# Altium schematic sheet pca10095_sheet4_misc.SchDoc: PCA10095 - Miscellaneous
size A3; Organization: Nordic Semiconductor; DocumentNumber: 4; SheetNumber: 4; SheetTotal: 6; CompanyName: Nordic Semiconductor
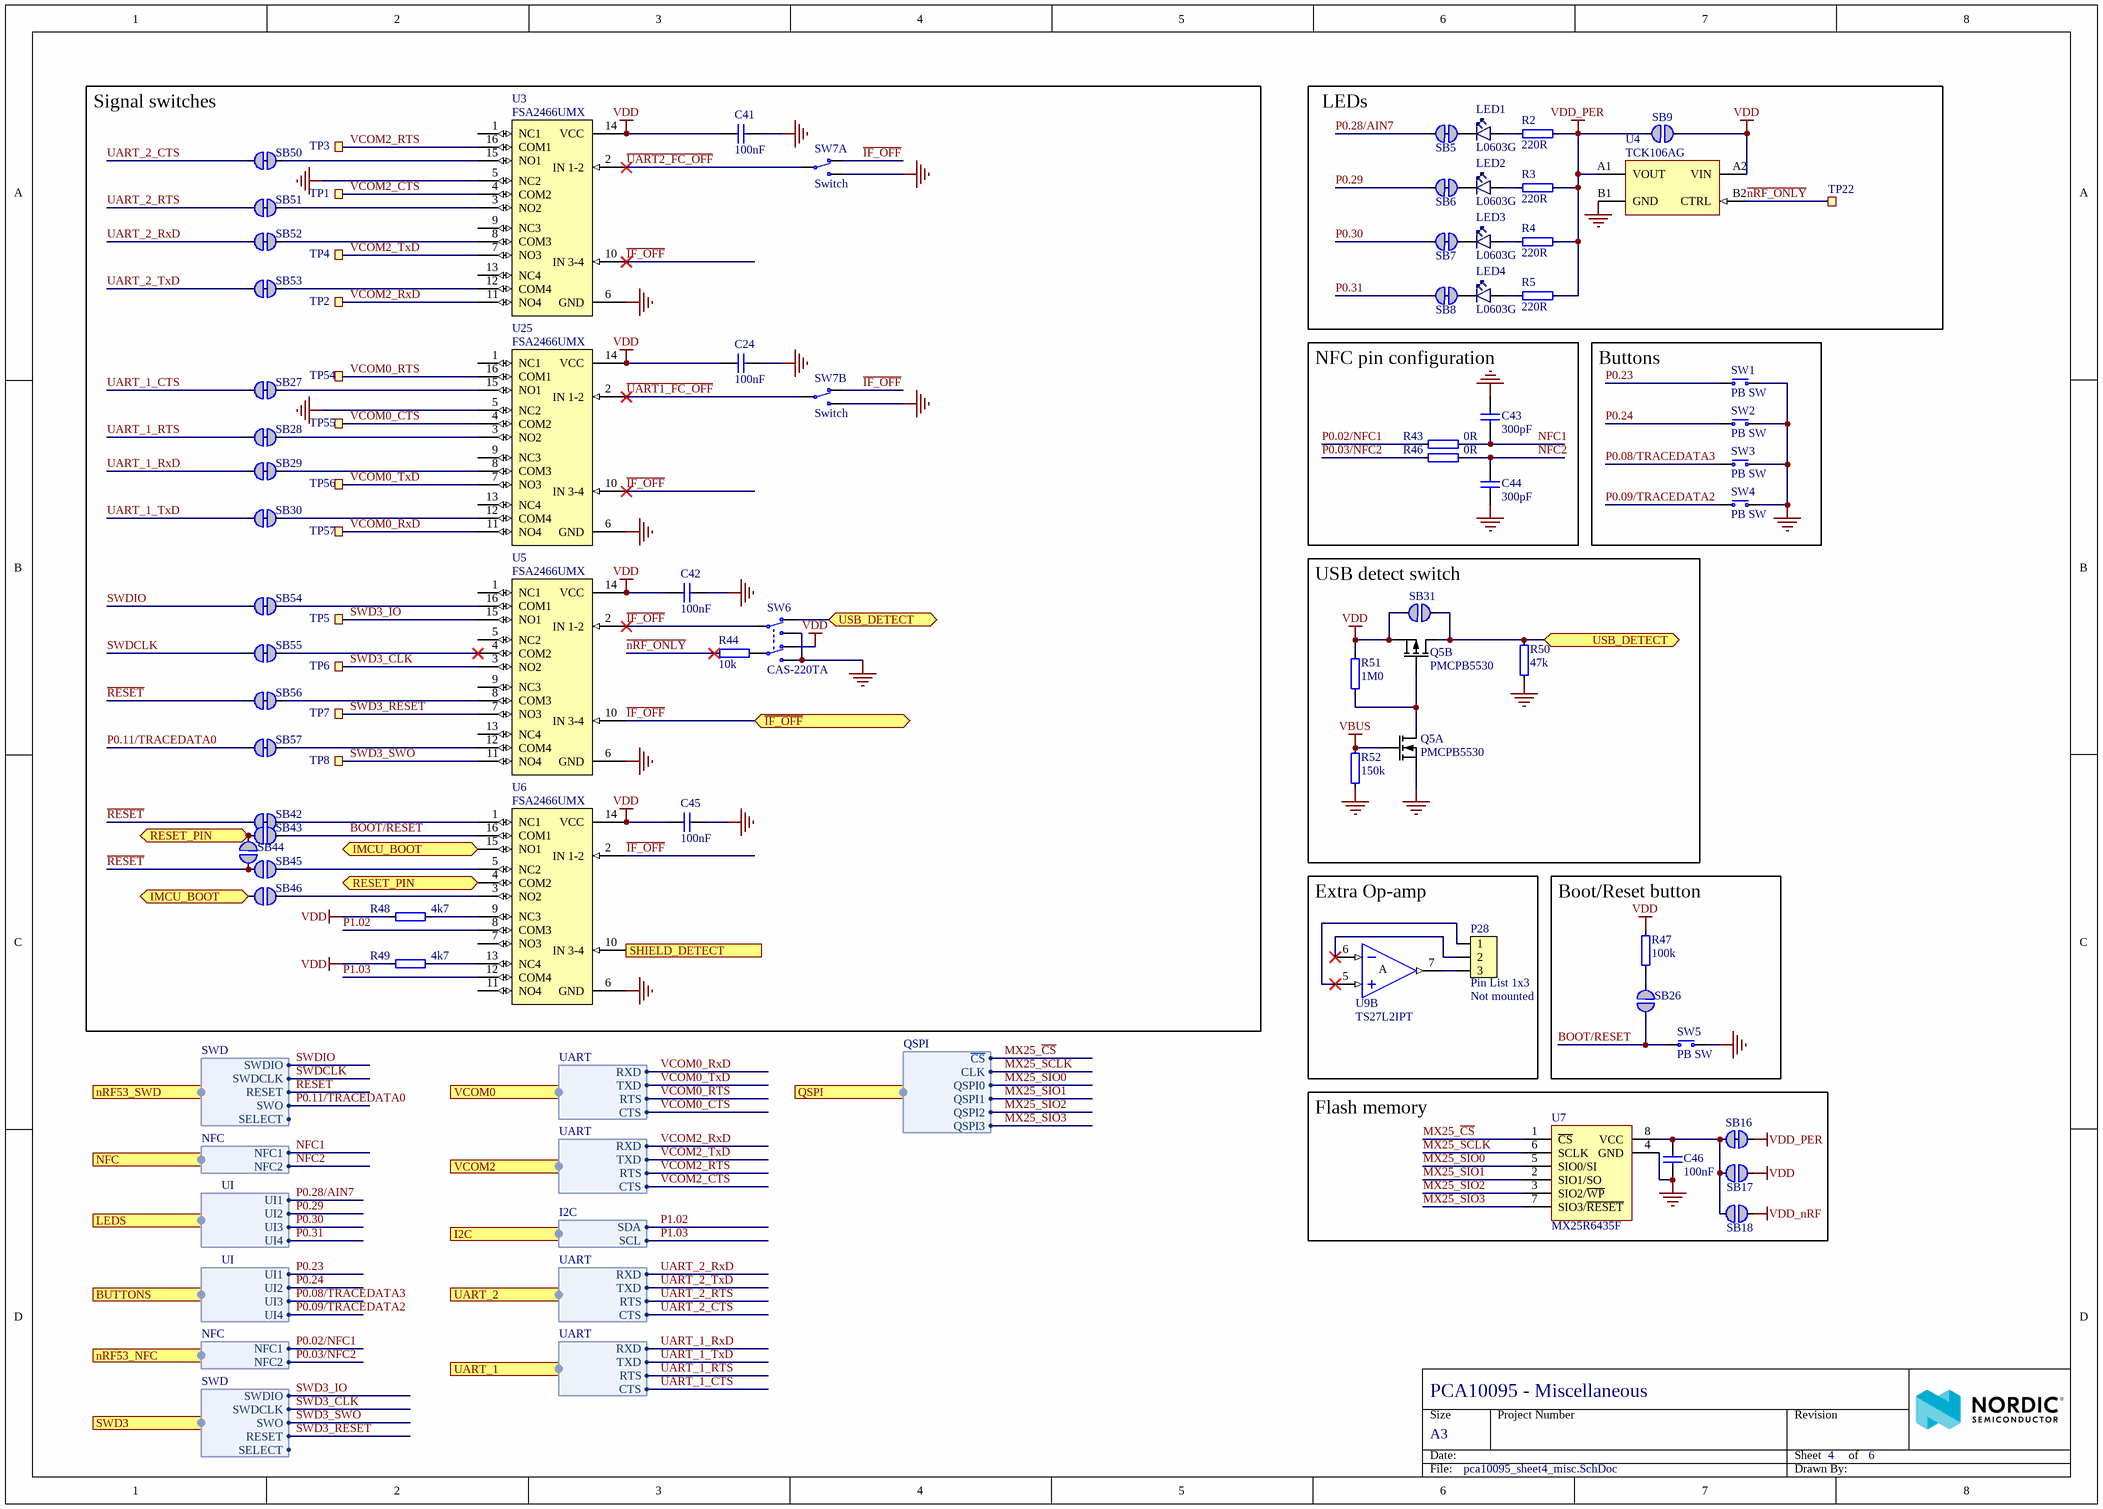
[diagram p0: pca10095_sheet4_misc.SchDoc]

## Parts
C24  100nF  [CAPC0603X03L_C]
C41  100nF  [CAPC0603X03L_C]
C42  100nF  [CAPC0603X03L_C]
C43  300pF  [CAPC1005X04L]
C44  300pF  [CAPC1005X04L]
C45  100nF  [CAPC0603X03L_C]
C46  100nF  [CAPC0603X03L_C]
LED1  L0603G  [LED_0603_G]
LED2  L0603G  [LED_0603_G]
LED3  L0603G  [LED_0603_G]
LED4  L0603G  [LED_0603_G]
P28  Pin List 1x3  Assembly: Not mounted  [LIST_1x3-NC]
Q5  PMCPB5530  [PMCPB5530X]  (parts A,B of 2)
R2  220R  [RESC0603X03L_C]
R3  220R  [RESC0603X03L_C]
R4  220R  [RESC0603X03L_C]
R5  220R  [RESC0603X03L_C]
R43  0R  [RESC0603X03L_C]
R44  10k  [RESC0603X03L_C]
R46  0R  [RESC0603X03L_C]
R47  100k  [RESC0603X03L_C]
R48  4k7  [RESC0603X03L_C]
R49  4k7  [RESC0603X03L_C]
R50  47k  [RESC0603X03L_C]
R51  1M0  [RESC0603X03L_C]
R52  150k  [RESC0603X03L_C]
SB5  Solderbridge  [Solderbridge_Shorted]  (value not drawn)  (net tie, no BOM)
SB6  Solderbridge  [Solderbridge_Shorted]  (value not drawn)  (net tie, no BOM)
SB7  Solderbridge  [Solderbridge_Shorted]  (value not drawn)  (net tie, no BOM)
SB8  Solderbridge  [Solderbridge_Shorted]  (value not drawn)  (net tie, no BOM)
SB9  Solderbridge  [Solderbridge]  (value not drawn)  (no BOM)
SB16  Solderbridge  [Solderbridge_Shorted]  (value not drawn)  (net tie, no BOM)
SB17  Solderbridge  [Solderbridge]  (value not drawn)  (no BOM)
SB18  Solderbridge  [Solderbridge]  (value not drawn)  (no BOM)
SB26  Solderbridge  [Solderbridge]  (value not drawn)  (no BOM)
SB27  Solderbridge  [Solderbridge_Shorted]  (value not drawn)  (net tie, no BOM)
SB28  Solderbridge  [Solderbridge_Shorted]  (value not drawn)  (net tie, no BOM)
SB29  Solderbridge  [Solderbridge_Shorted]  (value not drawn)  (net tie, no BOM)
SB30  Solderbridge  [Solderbridge_Shorted]  (value not drawn)  (net tie, no BOM)
SB31  Solderbridge  [Solderbridge]  (value not drawn)  (no BOM)
SB42  Solderbridge  [Solderbridge_Shorted]  (value not drawn)  (net tie, no BOM)
SB43  Solderbridge  [Solderbridge]  (value not drawn)  (no BOM)
SB44  Solderbridge  [Solderbridge]  (value not drawn)  (no BOM)
SB45  Solderbridge  [Solderbridge]  (value not drawn)  (no BOM)
SB46  Solderbridge  [Solderbridge]  (value not drawn)  (no BOM)
SB50  Solderbridge  [Solderbridge_Shorted]  (value not drawn)  (net tie, no BOM)
SB51  Solderbridge  [Solderbridge_Shorted]  (value not drawn)  (net tie, no BOM)
SB52  Solderbridge  [Solderbridge_Shorted]  (value not drawn)  (net tie, no BOM)
SB53  Solderbridge  [Solderbridge_Shorted]  (value not drawn)  (net tie, no BOM)
SB54  Solderbridge  [Solderbridge_Shorted]  (value not drawn)  (net tie, no BOM)
SB55  Solderbridge  [Solderbridge_Shorted]  (value not drawn)  (net tie, no BOM)
SB56  Solderbridge  [Solderbridge_Shorted]  (value not drawn)  (net tie, no BOM)
SB57  Solderbridge  [Solderbridge_Shorted]  (value not drawn)  (net tie, no BOM)
SW1  PB SW  [Switch-PB-6.2x6.3mm-SMD]
SW2  PB SW  [Switch-PB-6.2x6.3mm-SMD]
SW3  PB SW  [Switch-PB-6.2x6.3mm-SMD]
SW4  PB SW  [Switch-PB-6.2x6.3mm-SMD]
SW5  PB SW  [Switch-PB-6.2x6.3mm-SMD]
SW6  CAS-220TA  [CAS-220TA]
SW7  Switch  [CAS-D20A]  (parts A,B of 2)
TP1  Ø1.5mm,SMD  [TP_SMD_Ø1.5mm]  (value not drawn)  (no BOM)
TP2  Ø1.5mm,SMD  [TP_SMD_Ø1.5mm]  (value not drawn)  (no BOM)
TP3  Ø1.5mm,SMD  [TP_SMD_Ø1.5mm]  (value not drawn)  (no BOM)
TP4  Ø1.5mm,SMD  [TP_SMD_Ø1.5mm]  (value not drawn)  (no BOM)
TP5  Ø1.5mm,SMD  [TP_SMD_Ø1.5mm]  (value not drawn)  (no BOM)
TP6  Ø1.5mm,SMD  [TP_SMD_Ø1.5mm]  (value not drawn)  (no BOM)
TP7  Ø1.5mm,SMD  [TP_SMD_Ø1.5mm]  (value not drawn)  (no BOM)
TP8  Ø1.5mm,SMD  [TP_SMD_Ø1.5mm]  (value not drawn)  (no BOM)
TP22  Ø1.5mm,SMD  [TP_SMD_Ø1.5mm]  (value not drawn)  (no BOM)
TP54  Ø1.5mm,SMD  [TP_SMD_Ø1.5mm]  (value not drawn)  (no BOM)
TP55  Ø1.5mm,SMD  [TP_SMD_Ø1.5mm]  (value not drawn)  (no BOM)
TP56  Ø1.5mm,SMD  [TP_SMD_Ø1.5mm]  (value not drawn)  (no BOM)
TP57  Ø1.5mm,SMD  [TP_SMD_Ø1.5mm]  (value not drawn)  (no BOM)
U3  FSA2466UMX  [XQFN40P180X260X50-16N]
U4  TCK106AG  [BGA4C40P2X2_76X76X62]
U5  FSA2466UMX  [XQFN40P180X260X50-16N]
U6  FSA2466UMX  [XQFN40P180X260X50-16N]
U7  MX25R6435F  [SON127P600X80_HS-9N]
U9  TS27L2IPT  [TSOP65P640X120-8N]  (part B of 2)
U25  FSA2466UMX  [XQFN40P180X260X50-16N]

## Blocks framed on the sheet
Signal switches: C24 C41 C42 C45 R44 R48 R49 SB27-SB30 SB42-SB46 SB50-SB57 SW6 SW7 TP1-TP8 TP54-TP57 U3 U5 U6 U25
LEDs: LED1-LED4 R2-R5 SB5-SB9 TP22 U4
NFC pin configuration: C43 C44 R43 R46
Buttons: SW1-SW4
USB detect switch: Q5 R50-R52 SB31
Extra Op-amp: P28 U9
Boot/Reset button: R47 SB26 SW5
Flash memory: C46 SB16-SB18 U7

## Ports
BUTTONS (harness UI), I2C (harness I2C), IMCU_BOOT (bidir), LEDS (harness UI), NFC (harness NFC), nRF53_NFC (harness NFC), nRF53_SWD (harness SWD), QSPI (harness QSPI), RESET_PIN (bidir), SHIELD_DETECT (in), SWD3 (harness SWD), UART_1 (harness UART), UART_2 (harness UART), USB_DETECT (bidir), VCOM0 (harness UART), VCOM2 (harness UART), ~{IF_OFF} (bidir)

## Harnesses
SWD: SWDIO, SWDCLK, SWO, RESET, SELECT
NFC: NFC2, NFC1
UI: UI4, UI3, UI2, UI1
QSPI: ~{CS}, QSPI0, CLK, QSPI1, QSPI2, QSPI3
UART: RTS, CTS, RXD, TXD
I2C: SCL, SDA

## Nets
GND: C24.1 C41.1 C42.1 C43.2 C44.1 C45.1 C46.1 Q5.1(S1) R50.2 R52.2 SW1.1(N.O) SW2.1(N.O) SW3.1(N.O) SW4.1(N.O) SW5.1(N.O) SW6.1(N.O-1) SW6.4(N.O-2) SW7.1(N.O) SW7.4(N.O) U3.5(NC2) U3.6(GND) U4.B1(GND) U5.6(GND) U6.6(GND) U7.4(GND) U7.9(GND) U25.5(NC2) U25.6(GND)
VBUS: Q5.2(G1) R52.1
VDD: C24.2 C41.2 C42.2 C45.2 Q5.4(S2) R47.2 R48.1 R49.1 R51.1 SB9.1 SB17.1 SB31.1 SW6.6(N.C-2) U3.14(VCC) U4.A2(VIN) U5.14(VCC) U6.14(VCC) U25.14(VCC)
VDD_nRF: SB18.1
VDD_PER: R2.2 R3.2 R4.2 R5.2 SB9.2 SB16.1 U4.A1(VOUT)
BOOT/RESET: SB26.1 SB43.1 SW5.2(COM) U6.16(COM1)
~{IF_OFF}: SW6.2(COM-1) SW7.3(N.C) SW7.6(N.C) U3.10(IN_3-4) U5.2(IN_1-2) U5.10(IN_3-4) U6.2(IN_1-2) U25.10(IN_3-4) ; port ~{IF_OFF}
IMCU_BOOT: SB46.2 U6.15(NO1) ; port IMCU_BOOT
MX25_~{CS}: U7.1(~{CS}) ; port QSPI.~{CS}
MX25_SCLK: U7.6(SCLK) ; port QSPI.CLK
MX25_SIO0: U7.5(SIO0/SI) ; port QSPI.QSPI0
MX25_SIO1: U7.2(SIO1/SO) ; port QSPI.QSPI1
MX25_SIO2: U7.3(SIO2/~{WP}) ; port QSPI.QSPI2
MX25_SIO3: U7.7(SIO3/~{RESET}) ; port QSPI.QSPI3
~{nRF_ONLY}: R44.1 TP22.1 U4.B2(CTRL)
NFC1: C43.1 R43.1 ; port NFC.NFC1
NFC2: C44.2 R46.1 ; port NFC.NFC2
P0.02/NFC1: R43.2 ; port nRF53_NFC.NFC1
P0.03/NFC2: R46.2 ; port nRF53_NFC.NFC2
P0.08/TRACEDATA3: SW3.2(COM) ; port BUTTONS.UI3
P0.09/TRACEDATA2: SW4.2(COM) ; port BUTTONS.UI4
P0.11/TRACEDATA0: SB57.1 ; port nRF53_SWD.SWO
P0.23: SW1.2(COM) ; port BUTTONS.UI1
P0.24: SW2.2(COM) ; port BUTTONS.UI2
P0.28/AIN7: SB5.1 ; port LEDS.UI1
P0.29: SB6.1 ; port LEDS.UI2
P0.30: SB7.1 ; port LEDS.UI3
P0.31: SB8.1 ; port LEDS.UI4
P1.02: U6.8(COM3) ; port I2C.SDA
P1.03: U6.12(COM4) ; port I2C.SCL
~{RESET}: SB42.2 SB44.2 SB45.2 SB56.1 ; port nRF53_SWD.RESET
RESET_PIN: SB43.2 SB44.1 U6.4(COM2) ; port RESET_PIN
SHIELD_DETECT: U6.10(IN_3-4) ; port SHIELD_DETECT
SWD3_CLK: TP6.1 U5.3(NO2) ; port SWD3.SWDCLK
SWD3_IO: TP5.1 U5.15(NO1) ; port SWD3.SWDIO
SWD3_RESET: TP7.1 U5.7(NO3) ; port SWD3.RESET
SWD3_SWO: TP8.1 U5.11(NO4) ; port SWD3.SWO
SWDCLK: SB55.1 ; port nRF53_SWD.SWDCLK
SWDIO: SB54.1 ; port nRF53_SWD.SWDIO
~{UART1_FC_OFF}: SW7.5(COM) U25.2(IN_1-2)
~{UART2_FC_OFF}: SW7.2(COM) U3.2(IN_1-2)
UART_1_CTS: SB27.1 ; port UART_1.CTS
UART_1_RTS: SB28.1 ; port UART_1.RTS
UART_1_RxD: SB29.1 ; port UART_1.RXD
UART_1_TxD: SB30.1 ; port UART_1.TXD
UART_2_CTS: SB50.1 ; port UART_2.CTS
UART_2_RTS: SB51.1 ; port UART_2.RTS
UART_2_RxD: SB52.1 ; port UART_2.RXD
UART_2_TxD: SB53.1 ; port UART_2.TXD
USB_DETECT: Q5.3(D2) R50.1 SB31.2 SW6.3(N.C-1) ; port USB_DETECT
VCOM0_CTS: TP55.1 U25.4(COM2) ; port VCOM0.CTS
VCOM0_RTS: TP54.1 U25.16(COM1) ; port VCOM0.RTS
VCOM0_RxD: TP57.1 U25.11(NO4) ; port VCOM0.RXD
VCOM0_TxD: TP56.1 U25.7(NO3) ; port VCOM0.TXD
VCOM2_CTS: TP1.1 U3.4(COM2) ; port VCOM2.CTS
VCOM2_RTS: TP3.1 U3.16(COM1) ; port VCOM2.RTS
VCOM2_RxD: TP2.1 U3.11(NO4) ; port VCOM2.RXD
VCOM2_TxD: TP4.1 U3.7(NO3) ; port VCOM2.TXD
NetC46_2: C46.2 SB16.2 SB17.2 SB18.2 U7.8(VCC)
NetLED1_1: LED1.1(C) SB5.2
NetLED1_2: LED1.2(A) R2.1
NetLED2_1: LED2.1(C) SB6.2
NetLED2_2: LED2.2(A) R3.1
NetLED3_1: LED3.1(C) SB7.2
NetLED3_2: LED3.2(A) R4.1
NetLED4_1: LED4.1(C) SB8.2
NetLED4_2: LED4.2(A) R5.1
NetP28_1: P28.1 U9.5(IN2+)
NetP28_2: P28.2 U9.6(IN2-)
NetP28_3: P28.3 U9.7(OUT2)
NetQ5_5: Q5.5(G2) Q5.6(D1) R51.2
NetR44_2: R44.2 SW6.5(COM-2)
NetR47_1: R47.1 SB26.2
NetR48_2: R48.2 U6.9(NC3)
NetR49_2: R49.2 U6.13(NC4)
NetSB27_2: SB27.2 U25.15(NO1)
NetSB28_2: SB28.2 U25.3(NO2)
NetSB29_2: SB29.2 U25.8(COM3)
NetSB30_2: SB30.2 U25.12(COM4)
NetSB42_1: SB42.1 U6.1(NC1)
NetSB45_1: SB45.1 U6.5(NC2)
NetSB46_1: SB46.1 U6.3(NO2)
NetSB50_2: SB50.2 U3.15(NO1)
NetSB51_2: SB51.2 U3.3(NO2)
NetSB52_2: SB52.2 U3.8(COM3)
NetSB53_2: SB53.2 U3.12(COM4)
NetSB54_2: SB54.2 U5.16(COM1)
NetSB55_2: SB55.2 U5.4(COM2)
NetSB56_2: SB56.2 U5.8(COM3)
NetSB57_2: SB57.2 U5.12(COM4)

Not connected (* = marked no-connect by the designer): U3 1(NC1) 9(NC3) 13(NC4); U5 1(NC1) 5(NC2) 9(NC3) 13(NC4); U6 7(NO3) 11(NO4); U25 1(NC1) 9(NC3) 13(NC4)

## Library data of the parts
C24 C41 C42 C45 C46 = C0201-100n: Capacitor, X5R, ±10%; Manufacturer: N.A.; Part number IPS: 00000001248, 00000002505; Note: 16V; Pad Count: 2
C43 C44 = C0402-300p: Capacitor, NP0, ±5%; Manufacturer: N.A.; Part number IPS: 00000007788; Note: 50V; Artikkelnr Noca: 20020004; Pad Count: 2
LED1-LED4 = VS 25C7M5: LED, Green, 0603, 573nm, Vf=2.0V, 24mcd, - 40 to +85°C; Manufacturer: Victory Electronics; Part number IPS: 00000001274, 00000009961; Note: N.A.; Artikkelnr Noca: 13019193; Pad Count: 2
P28 = Pin List 1x3, N.C.: Pin List 1x3, 2.54mm (100mil); Manufacturer: N.A.; Pad Count: 3
Q5 = PMCPB5530X,115: Mosfet Array N and P-Channel 20V 4A (Ta), 3.4A (Ta) 490mW Surface Mount 6-HUSON-EP (2x2); Manufacturer: Nexperia; Part number IPS: 00000001918; Note: N.A.; Pad Count: 8
R2-R5 = R0201-220: Resistor, ±1%, 0.05W; Manufacturer: N.A.; Part number IPS: 00000000863; Note: Chip Res 1%; Pad Count: 2
R43 R46 = R0201-0R: Resistor, ±5%, 0.05W; Manufacturer: N.A.; Part number IPS: 00000003245; Note: Chip Res 5%; Pad Count: 2
R44 = R0201-10k: Resistor, ±1%, 0.05W; Manufacturer: N.A.; Part number IPS: 00000001255; Note: Chip Res 1%; Pad Count: 2
R47 = R0201-100k: Resistor, ±1%, 0.05W; Manufacturer: N.A.; Part number IPS: 00000001419; Note: Chip Res 1%; Pad Count: 2
R48 R49 = R0201-4k7: Resistor, ±1%, 0.05W; Manufacturer: N.A.; Part number IPS: 00000001706; Note: Chip Res 1%; Pad Count: 2
R50 = R0201-47k: Resistor, ±1%, 0.05W; Manufacturer: N.A.; Part number IPS: 00000001423; Note: Chip Res 1%; Pad Count: 2
R51 = R0201-1M0: Resistor, ±1%, 0.05W; Manufacturer: N.A.; Part number IPS: 00000001418; Note: Chip Res 1%; Pad Count: 2
R52 = R0201-150k: Resistor, ±1%, 0.05W; Manufacturer: N.A.; Part number IPS: 00000001422; Note: Chip Res 1%; Pad Count: 2
SB5-SB8 SB16 SB27-SB30 SB42 SB50-SB57 = Solderbridge Shorted: Shorted Solderbridge; Manufacturer: N.A.; Pad Count: 2
SB9 SB17 SB18 SB26 SB31 SB43-SB46 = Solderbridge: Manufacturer: N.A.; Pad Count: 2
SW1-SW5 = Switch-PB-6.2x6.3mm-SMD: Tactile Switch, SPNO, SMD, 160gf, 6.2x6.3x2.5mm; Manufacturer: Dailywell; Manufacturer Part Number: TS604VM1-025BR-R; Part number IPS: 00000007812; Note: N.A.; Artikkelnr Noca: 50019106; Pad Count: 4
SW6 = CAS-220TA: Slide Switch DPDT J Hook; Manufacturer: Copal Electronics Inc; Part number IPS: 00000009983; Note: N.A.; Artikkelnr Noca: 50019042; Pad Count: 6
SW7 = CAS-D20TA: SMD slide Switch 2xSPDT; Manufacturer: Copal Electronics Inc; Pad Count: 6; Note: N.A.
TP1-TP8 TP22 TP54-TP57 = TP_SMD_Ø1.5MM: 1.5mm circular SMD testpad; Manufacturer: Nordic Semiconductor; Manufacturer Part Number: N.A.; Pad Count: 1
U3 U5 U6 U25 = FSA2466UMX: Data / Audio Low-Voltage Dual DPDT Analog Switch; Manufacturer: ON Semiconductor; Part number IPS: 00000009986; Note: N.A.; Artikkelnr Noca: 15070069; Pad Count: 16
U4 = TCK106AG: 1.0 A Load Switch IC with Slew Rate Control Driver in Ultra Small Package; Manufacturer: Toshiba; Manufacturer Part Number: TCK106AG,LF; Part number IPS: 00000004390; Note: N.A.; Pad Count: 4
U7 = MX25R6435FZNIL0: Ultra low power, 64M-bit, serial multi I/O flash memory; Manufacturer: Macronix; Part number IPS: 00000004370; Note: N.A.; Artikkelnr Noca: 15020015; Pad Count: 8
U9 = TS27L2IPT: Precision very low power CMOS dual operational amplifier; Manufacturer: STMicroelectronics; Part number IPS: 00000009991; Note: N.A.; Artikkelnr Noca: 17010019; Pad Count: 8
